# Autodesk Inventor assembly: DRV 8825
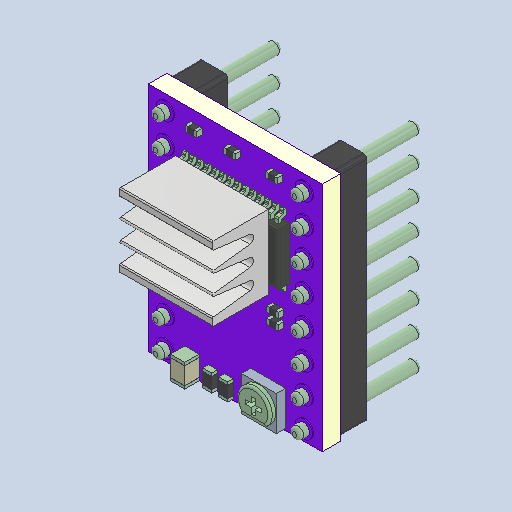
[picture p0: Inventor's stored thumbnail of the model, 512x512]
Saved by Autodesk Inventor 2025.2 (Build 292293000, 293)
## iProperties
Created: 2025-04
Part Number: DRV 8825
Description: PART--DESC
Document SubType Name: Assembly
Designer: BennF
Author: BennF
Revision Number: NONE
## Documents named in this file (9)
- C:\Users\BennF\Nextcloud\Benutzer\CNC JarBeRi\existing parts\Electronics\RepRap A4988 Shied (USE WITHOUT ARDUINO)\reprap-a4988-1.snapshot.1\RepRap\RepRap\DRV 8825.iam
- C:\Users\BennF\Nextcloud\Benutzer\CNC JarBeRi\existing parts\Electronics\RepRap A4988 Shied (USE WITHOUT ARDUINO)\reprap-a4988-1.snapshot.1\RepRap\RepRap\DRV 8825 Geometry.ipt
- C:\Users\BennF\Nextcloud\Benutzer\CNC JarBeRi\existing parts\Electronics\RepRap A4988 Shied (USE WITHOUT ARDUINO)\reprap-a4988-1.snapshot.1\RepRap\RepRap\PCB.ipt
- C:\Users\BennF\Nextcloud\Benutzer\CNC JarBeRi\existing parts\Electronics\RepRap A4988 Shied (USE WITHOUT ARDUINO)\reprap-a4988-1.snapshot.1\RepRap\RepRap\SMD Pot.ipt
- C:\Users\BennF\Nextcloud\Benutzer\CNC JarBeRi\existing parts\Electronics\RepRap A4988 Shied (USE WITHOUT ARDUINO)\reprap-a4988-1.snapshot.1\RepRap\RepRap\0603 Resistor.ipt
- C:\Users\BennF\Nextcloud\Benutzer\CNC JarBeRi\existing parts\Electronics\RepRap A4988 Shied (USE WITHOUT ARDUINO)\reprap-a4988-1.snapshot.1\RepRap\RepRap\0805 Capacitor.ipt
- C:\Users\BennF\Nextcloud\Benutzer\CNC JarBeRi\existing parts\Electronics\RepRap A4988 Shied (USE WITHOUT ARDUINO)\reprap-a4988-1.snapshot.1\RepRap\RepRap\0402 Resistor.ipt
- C:\Users\BennF\Nextcloud\Benutzer\CNC JarBeRi\existing parts\Electronics\RepRap A4988 Shied (USE WITHOUT ARDUINO)\reprap-a4988-1.snapshot.1\RepRap\RepRap\DRV8825 IC.ipt
- C:\Users\BennF\Nextcloud\Benutzer\CNC JarBeRi\existing parts\Electronics\RepRap A4988 Shied (USE WITHOUT ARDUINO)\reprap-a4988-1.snapshot.1\RepRap\RepRap\8 pin Header.ipt
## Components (16 placed, 8 different names)
1. DRV 8825 Geometry
2. PCB
3. SMD Pot
4. 0603 Resistor
5. 0603 Resistor:1
6. 0805 Capacitor
7. 0402 Resistor
8. 0402 Resistor:1
9. 0402 Resistor:2
10. 0402 Resistor:3
11. 0402 Resistor:4
12. 0402 Resistor:5
13. 0402 Resistor:6
14. DRV8825 IC
15. 8 pin Header
16. 8 pin Header:1
